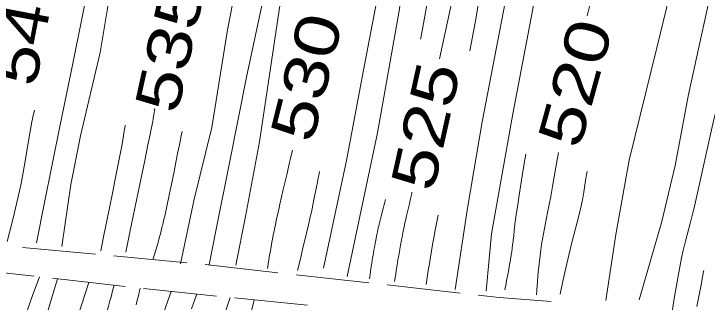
# Model space of a CAD drawing. Extents: x 2361284 to 2366480, y 6976556 to 6985346.
# Drawn here: x 2364811.3 to 2364887, y 6979187.4 to 6979218.9 of the extents above; entities that cross this region are included whole.
import ezdxf
from ezdxf.enums import TextEntityAlignment as Align

# ---------------------------------------------------------------- set-up
doc = ezdxf.new("R2010")
doc.units = 0
doc.header["$LTSCALE"] = 1.9
for name, color, linetype, lineweight in [('12', 7, 'Continuous', 13), ('13', 7, 'Continuous', 13), ('6', 7, 'Continuous', 13)]:
    doc.layers.add(name, color=color, linetype=linetype, lineweight=lineweight)

msp = doc.modelspace()

# ---------------------------------------------------------------- linework, layer by layer
at = {"layer": '12'}
for points in [[(2364928.338, 6979404.773), (2364927.195, 6979401.991), (2364924.932, 6979395.96), (2364922.532, 6979389.637), (2364919.419, 6979381.457), (2364916.6, 6979372.929), (2364914.535, 6979364.97), (2364911.915, 6979356.603), (2364906.81, 6979342.444), (2364903.391, 6979331.771), (2364900.674, 6979323.105), (2364897.677, 6979314.345), (2364893.693, 6979298.897), (2364889.623, 6979284.088), (2364887.079, 6979275.043), (2364882.952, 6979258.982), (2364879.363, 6979246.318), (2364877.403, 6979235.749), (2364874.144, 6979219.817), (2364873.874, 6979218.664)], [(2364892.809, 6979393.874), (2364890.358, 6979378.279), (2364887.083, 6979364.069), (2364883.826, 6979351.046), (2364881.758, 6979340.367), (2364879.074, 6979326.15), (2364876.929, 6979314.058), (2364874.851, 6979303.198), (2364871.819, 6979287.628), (2364868.255, 6979272.234), (2364866.777, 6979261.469), (2364864.79, 6979249.63), (2364863.428, 6979242.396), (2364861.678, 6979234.019), (2364859.472, 6979222.058), (2364857.728, 6979213.971)], [(2364826.658, 6979208.535), (2364826.633, 6979208.38), (2364826.588, 6979208.071), (2364826.529, 6979207.657), (2364826.497, 6979207.451), (2364826.473, 6979207.314), (2364826.461, 6979207.245), (2364826.441, 6979207.143), (2364826.269, 6979206.286), (2364826.153, 6979205.715), (2364825.92, 6979204.573), (2364825.566, 6979202.86), (2364824.854, 6979199.437), (2364823.944, 6979195.061), (2364823.487, 6979192.874)], [(2364841.682, 6979203.998), (2364841.479, 6979203.098), (2364841.341, 6979202.498), (2364841.063, 6979201.299), (2364840.69, 6979199.701), (2364840.505, 6979198.902), (2364840.32, 6979198.103), (2364840.229, 6979197.703), (2364840.049, 6979196.902), (2364839.96, 6979196.501), (2364839.829, 6979195.9), (2364839.791, 6979195.724), (2364839.718, 6979195.371), (2364839.646, 6979195.017), (2364839.6, 6979194.782), (2364839.51, 6979194.31), (2364839.444, 6979193.955), (2364839.402, 6979193.719), (2364839.318, 6979193.245), (2364839.278, 6979193.008), (2364839.197, 6979192.534), (2364839.119, 6979192.06), (2364838.965, 6979191.111)], [(2364870.726, 6979203.763), (2364870.429, 6979202.163), (2364870.068, 6979200.024), (2364869.882, 6979198.956), (2364869.546, 6979197.214), (2364869.086, 6979194.893), (2364868.881, 6979193.726), (2364868.789, 6979193.12), (2364868.64, 6979191.904), (2364868.524, 6979190.684), (2364868.344, 6979188.24)], [(2364854.737, 6979199.412), (2364854.707, 6979199.27), (2364854.646, 6979198.988), (2364854.583, 6979198.705), (2364854.541, 6979198.517), (2364854.454, 6979198.142), (2364854.321, 6979197.578), (2364854.144, 6979196.827), (2364854.057, 6979196.451), (2364853.973, 6979196.075), (2364853.933, 6979195.886), (2364853.873, 6979195.603), (2364853.828, 6979195.385), (2364853.741, 6979194.949), (2364853.656, 6979194.513), (2364853.601, 6979194.222), (2364853.493, 6979193.639), (2364853.414, 6979193.202), (2364853.363, 6979192.91), (2364853.262, 6979192.326), (2364853.212, 6979192.034), (2364853.116, 6979191.449), (2364853.021, 6979190.864), (2364852.959, 6979190.474), (2364852.838, 6979189.693)], [(2364822.232, 6979189.262), (2364822.028, 6979188.509), (2364821.925, 6979188.132), (2364821.768, 6979187.569), (2364821.608, 6979187.006), (2364821.526, 6979186.725), (2364821.382, 6979186.236), (2364821.285, 6979185.91), (2364821.09, 6979185.259), (2364820.794, 6979184.283), (2364820.198, 6979182.332)], [(2364837.507, 6979187.687), (2364837.181, 6979186.34), (2364837.003, 6979185.671), (2364836.805, 6979185.008), (2364836.696, 6979184.679), (2364836.065, 6979182.868), (2364834.767, 6979179.26), (2364833.262, 6979175.106), (2364832.486, 6979173.038), (2364832.245, 6979172.433), (2364832.075, 6979172.034), (2364831.722, 6979171.24), (2364830.612, 6979168.883), (2364830.076, 6979167.696), (2364829.575, 6979166.488), (2364828.928, 6979164.867), (2364828.591, 6979164.061), (2364828.332, 6979163.478), (2364828.153, 6979163.092), (2364827.78, 6979162.329), (2364827.188, 6979161.201), (2364826.774, 6979160.458), (2364826.491, 6979159.965), (2364825.909, 6979158.985)]]:
    msp.add_lwpolyline(points, dxfattribs=at)
at = {"layer": '13'}
for points in [[(2364953.546, 6979538.739), (2364951.73, 6979532.022), (2364949.096, 6979523.986), (2364946.595, 6979516.742), (2364944.83, 6979511.974), (2364942.013, 6979505.338), (2364937.966, 6979497.559), (2364932.421, 6979488.705), (2364927.679, 6979480.421), (2364924.672, 6979472.712), (2364920.626, 6979462.822), (2364915.322, 6979451.562), (2364911.657, 6979441.586), (2364906.137, 6979424.832), (2364900.236, 6979404.905), (2364894.169, 6979384.497), (2364889.513, 6979361.892), (2364883.686, 6979331.134), (2364880.421, 6979314.802), (2364874.826, 6979288.987), (2364868.833, 6979255.629), (2364866.279, 6979245.533), (2364861.641, 6979217.898), (2364861.05, 6979214.832)], [(2364870.103, 6979395.469), (2364866.361, 6979379.951), (2364863.768, 6979364.397), (2364858.988, 6979344.49), (2364855.217, 6979323.473), (2364852.338, 6979308.515), (2364848.685, 6979292.098), (2364845.65, 6979275.81), (2364842.581, 6979257.779), (2364839.483, 6979242.818), (2364836.913, 6979229.113), (2364834.587, 6979217.121), (2364832.899, 6979206.464), (2364830.952, 6979198.645), (2364829.469, 6979191.601)], [(2364872.305, 6979393.189), (2364867.085, 6979367.959), (2364862.537, 6979345.583), (2364857.126, 6979321.501), (2364853.57, 6979304.246), (2364849.37, 6979285.254), (2364845.525, 6979261.637), (2364841.654, 6979239.599), (2364839.108, 6979223.374), (2364836.677, 6979211.96), (2364834.805, 6979202.631), (2364833.346, 6979195.208), (2364832.601, 6979191.511)], [(2364902.442, 6979388.496), (2364898.909, 6979378.251), (2364895.442, 6979367.308), (2364892.52, 6979358.089), (2364889.421, 6979342.179), (2364886.214, 6979327.108), (2364884.203, 6979315.668), (2364880.832, 6979299.925), (2364878.956, 6979291.176), (2364875.438, 6979276.273), (2364872.987, 6979265.748), (2364868.907, 6979247.848), (2364866.977, 6979231.029), (2364864.729, 6979219.157), (2364862.384, 6979207.105), (2364860.783, 6979197.689), (2364859.458, 6979188.806)], [(2364888.857, 6979387.816), (2364886.14, 6979373.829), (2364883.35, 6979361.173), (2364880.672, 6979346.266), (2364877.552, 6979332.665), (2364875.39, 6979321.204), (2364871.524, 6979303.897), (2364867.73, 6979288.569), (2364865.626, 6979275.27), (2364863.491, 6979261.068), (2364861.737, 6979249.881), (2364859.594, 6979240.71), (2364857.911, 6979228.444), (2364855.687, 6979216.201), (2364855.668, 6979216.101)], [(2364885.633, 6979387.166), (2364879.447, 6979356.225), (2364870.017, 6979315.143), (2364865.32, 6979288.546), (2364859.944, 6979257.614), (2364855.756, 6979235.263), (2364853.339, 6979219.189), (2364850.975, 6979205.896), (2364847.654, 6979190.234)], [(2364908.008, 6979386.729), (2364903.974, 6979371.438), (2364899.674, 6979357.767), (2364895.945, 6979347.011), (2364892.112, 6979333.694), (2364889.415, 6979322.838), (2364884.695, 6979302.772), (2364881.671, 6979289.572), (2364879.366, 6979278.59), (2364876.57, 6979263.432), (2364874.19, 6979251.75), (2364872.324, 6979240.781), (2364870.172, 6979231.57), (2364867.728, 6979218.266), (2364865.746, 6979207.957), (2364863.41, 6979194.874), (2364862.829, 6979188.638)], [(2364882.393, 6979382.925), (2364876.991, 6979358.992), (2364873.041, 6979339.994), (2364870.539, 6979327.549), (2364867.213, 6979313.495), (2364862.876, 6979287.923), (2364860.619, 6979274.882), (2364858.117, 6979260.436), (2364856.169, 6979250.728), (2364854.778, 6979238.224), (2364852.316, 6979227.771), (2364849.45, 6979212.742), (2364847.603, 6979202.893), (2364845.065, 6979191.149)], [(2364872.908, 6979381.345), (2364870.69, 6979371.582), (2364864.338, 6979345.53), (2364860.311, 6979326.271), (2364855.806, 6979305.698), (2364851.796, 6979283.558), (2364847.901, 6979262.029), (2364843.719, 6979236.958), (2364841.197, 6979225.644), (2364838.094, 6979204.894), (2364836.561, 6979196.769), (2364835.502, 6979191.448)], [(2364849.396, 6979370.92), (2364848.573, 6979366.983), (2364846.03, 6979355.707), (2364843.156, 6979341.449), (2364840.627, 6979328.684), (2364838.817, 6979319.187), (2364836.411, 6979308.243), (2364834.31, 6979294.723), (2364831.344, 6979281.614), (2364829.098, 6979270.582), (2364827.546, 6979261.336), (2364824.695, 6979247.758), (2364822.56, 6979236.757), (2364819.459, 6979222.127), (2364817.77, 6979213.621), (2364816.287, 6979206.576), (2364814.635, 6979198.31), (2364813.737, 6979193.881)], [(2364852.165, 6979368.826), (2364851.189, 6979365.187), (2364847.016, 6979345.686), (2364844.515, 6979333.121), (2364842.126, 6979320.348), (2364839.41, 6979306.292), (2364836.59, 6979290.443), (2364833.659, 6979277.916), (2364831.377, 6979267.613), (2364828.568, 6979255.806), (2364826.566, 6979244.516), (2364824.743, 6979236.378), (2364822.147, 6979223.413), (2364820.71, 6979214.639), (2364818.566, 6979205.578), (2364817.497, 6979200.257), (2364816.501, 6979193.508)], [(2364915.38, 6979337.136), (2364914.087, 6979333.233), (2364911.656, 6979323.859), (2364908.063, 6979311.535), (2364904.289, 6979298.388), (2364900.534, 6979285.191), (2364898.513, 6979277.952), (2364895.361, 6979266.471), (2364892.013, 6979255.67), (2364889.124, 6979246.101), (2364887.027, 6979237.43), (2364884.644, 6979228.188), (2364881.448, 6979215.156), (2364878.456, 6979202.896), (2364876.973, 6979194.793), (2364875.911, 6979187.612)], [(2364905.775, 6979286.201), (2364903.391, 6979280.309), (2364900.005, 6979268.315), (2364897.509, 6979258.231), (2364895.171, 6979249.629), (2364892.48, 6979238.112), (2364889.821, 6979229.606), (2364887.246, 6979220.712), (2364884.937, 6979210.069), (2364883.48, 6979202.314), (2364882.028, 6979196.211), (2364879.54, 6979187.697)], [(2364894.255, 6979230.319), (2364893.205, 6979226.471), (2364892.659, 6979224.553), (2364890.596, 6979217.543), (2364888.944, 6979211.885), (2364888.137, 6979209.05), (2364887.983, 6979208.486), (2364887.694, 6979207.354), (2364887.424, 6979206.217), (2364886.905, 6979203.938), (2364885.534, 6979197.704), (2364885.41, 6979197.185), (2364885.142, 6979196.152), (2364884.588, 6979194.09), (2364884.338, 6979193.053), (2364884.167, 6979192.257), (2364883.861, 6979190.658), (2364883.358, 6979187.808), (2364883.122, 6979186.381)], [(2364813.54, 6979208.38), (2364813.367, 6979207.619), (2364813.215, 6979206.906), (2364813.122, 6979206.43), (2364812.952, 6979205.473), (2364812.493, 6979202.593), (2364812.238, 6979201.157), (2364812.078, 6979200.359), (2364811.733, 6979198.769), (2364811.357, 6979197.187), (2364811.094, 6979196.134), (2364810.546, 6979194.031)], [(2364823.446, 6979206.734), (2364823.394, 6979206.445), (2364823.361, 6979206.252), (2364823.296, 6979205.866), (2364823.171, 6979205.093), (2364823.106, 6979204.707), (2364823.06, 6979204.45), (2364823.037, 6979204.322), (2364823, 6979204.13), (2364822.856, 6979203.398), (2364822.566, 6979201.935), (2364822.273, 6979200.472), (2364822.077, 6979199.497), (2364821.683, 6979197.547), (2364821.073, 6979194.534), (2364820.766, 6979193.028)], [(2364829.651, 6979206.053), (2364829.554, 6979205.568), (2364829.358, 6979204.599), (2364829.16, 6979203.631), (2364828.763, 6979201.694), (2364828.441, 6979200.13), (2364828.224, 6979199.088), (2364827.787, 6979197.005), (2364827.748, 6979196.823), (2364827.668, 6979196.46), (2364827.583, 6979196.098), (2364827.525, 6979195.858), (2364827.486, 6979195.697), (2364827.405, 6979195.377), (2364827.312, 6979195.017), (2364827.248, 6979194.778), (2364827.118, 6979194.3), (2364827.052, 6979194.061), (2364826.917, 6979193.583), (2364826.78, 6979193.106), (2364826.503, 6979192.153)], [(2364867.148, 6979203.569), (2364867.027, 6979202.779), (2364866.781, 6979201.199), (2364866.451, 6979199.093), (2364866.287, 6979198.039), (2364866.125, 6979196.986), (2364866.045, 6979196.459), (2364866.031, 6979196.363), (2364866.004, 6979196.171), (2364865.98, 6979195.978), (2364865.964, 6979195.85), (2364865.935, 6979195.593), (2364865.894, 6979195.207), (2364865.843, 6979194.692), (2364865.816, 6979194.435), (2364865.788, 6979194.177), (2364865.773, 6979194.049), (2364865.75, 6979193.856), (2364865.726, 6979193.667), (2364865.675, 6979193.288), (2364865.621, 6979192.91), (2364865.583, 6979192.659), (2364865.557, 6979192.491), (2364865.504, 6979192.156), (2364865.442, 6979191.78), (2364865.399, 6979191.529), (2364865.309, 6979191.028), (2364865.263, 6979190.778), (2364865.169, 6979190.277), (2364865.071, 6979189.777), (2364865.004, 6979189.444), (2364864.868, 6979188.777)], [(2364844.635, 6979201.665), (2364844.563, 6979201.263), (2364844.514, 6979200.995), (2364844.413, 6979200.459), (2364844.361, 6979200.192), (2364844.256, 6979199.657), (2364844.149, 6979199.123), (2364844.076, 6979198.768), (2364843.926, 6979198.057), (2364843.869, 6979197.791), (2364843.753, 6979197.259), (2364843.635, 6979196.728), (2364843.555, 6979196.373), (2364843.394, 6979195.665), (2364843.271, 6979195.135), (2364843.188, 6979194.781), (2364843.02, 6979194.074), (2364842.765, 6979193.013), (2364842.594, 6979192.306), (2364842.247, 6979190.892)], [(2364873.846, 6979201.662), (2364873.787, 6979201.343), (2364873.691, 6979200.702), (2364873.514, 6979199.416), (2364873.394, 6979198.779), (2364873.236, 6979198.083), (2364872.898, 6979196.697), (2364872.194, 6979193.932), (2364871.863, 6979192.544), (2364871.222, 6979189.706), (2364870.913, 6979188.285)], [(2364851.844, 6979198.614), (2364851.819, 6979198.507), (2364851.767, 6979198.292), (2364851.713, 6979198.078), (2364851.676, 6979197.936), (2364851.6, 6979197.651), (2364851.368, 6979196.799), (2364851.293, 6979196.514), (2364851.256, 6979196.372), (2364851.185, 6979196.086), (2364851.151, 6979195.943), (2364851.102, 6979195.727), (2364851.056, 6979195.515), (2364850.966, 6979195.09), (2364850.88, 6979194.664), (2364850.824, 6979194.381), (2364850.787, 6979194.191), (2364850.715, 6979193.812), (2364850.637, 6979193.385), (2364850.586, 6979193.1), (2364850.488, 6979192.53), (2364850.44, 6979192.245), (2364850.347, 6979191.674), (2364850.257, 6979191.102), (2364850.199, 6979190.721), (2364850.086, 6979189.957)], [(2364857.59, 6979196.929), (2364857.272, 6979195.279), (2364857.114, 6979194.454), (2364857.078, 6979194.266), (2364857.009, 6979193.889), (2364856.942, 6979193.512), (2364856.899, 6979193.26), (2364856.815, 6979192.756), (2364856.754, 6979192.378), (2364856.714, 6979192.126), (2364856.636, 6979191.621), (2364856.523, 6979190.863), (2364856.302, 6979189.346)], [(2364814.063, 6979190.184), (2364813.283, 6979188.027), (2364812.046, 6979184.505), (2364811.462, 6979182.765), (2364810.706, 6979180.437), (2364810.316, 6979179.277), (2364809.846, 6979177.976), (2364809.516, 6979177.116), (2364808.832, 6979175.403), (2364808.126, 6979173.681), (2364807.752, 6979172.829), (2364807.352, 6979171.991), (2364807.138, 6979171.578), (2364805.497, 6979168.542), (2364803.138, 6979164.219)], [(2364816.055, 6979189.953), (2364815.143, 6979186.945), (2364813.554, 6979181.568), (2364813.321, 6979180.817), (2364812.831, 6979179.323), (2364812.315, 6979177.837), (2364811.248, 6979174.876), (2364810.719, 6979173.458), (2364810.351, 6979172.52), (2364809.588, 6979170.651), (2364809.242, 6979169.84), (2364809.005, 6979169.303), (2364808.516, 6979168.237), (2364808.264, 6979167.707), (2364807.747, 6979166.654), (2364807.212, 6979165.609), (2364806.847, 6979164.916), (2364806.095, 6979163.537)], [(2364819.469, 6979189.576), (2364818.633, 6979186.978), (2364817.787, 6979184.44), (2364816.994, 6979182.011), (2364815.952, 6979178.767), (2364815.427, 6979177.146), (2364814.934, 6979175.697), (2364814.59, 6979174.736), (2364813.878, 6979172.821), (2364813.432, 6979171.674), (2364813.121, 6979170.915), (2364812.908, 6979170.413), (2364812.468, 6979169.414), (2364812.125, 6979168.67), (2364811.41, 6979167.196), (2364810.655, 6979165.738), (2364810.13, 6979164.775), (2364809.771, 6979164.136), (2364809.032, 6979162.865)], [(2364825.074, 6979188.939), (2364824.972, 6979188.503), (2364824.92, 6979188.285), (2364824.84, 6979187.959), (2364824.758, 6979187.634), (2364824.715, 6979187.472), (2364824.628, 6979187.148)], [(2364828.447, 6979188.601), (2364828.107, 6979187.671), (2364827.454, 6979185.802)], [(2364834.895, 6979187.942), (2364834.117, 6979185.645), (2364832.648, 6979181.33), (2364832.175, 6979179.894), (2364831.549, 6979177.978), (2364831.218, 6979177.026), (2364831.006, 6979176.457), (2364830.55, 6979175.331), (2364830.065, 6979174.217), (2364829.402, 6979172.737), (2364829.075, 6979171.996), (2364827.702, 6979168.892), (2364826.999, 6979167.346), (2364826.583, 6979166.467), (2364826.294, 6979165.887), (2364825.693, 6979164.739), (2364825.381, 6979164.172), (2364824.736, 6979163.047), (2364824.068, 6979161.934), (2364823.61, 6979161.198), (2364822.672, 6979159.735)], [(2364831.261, 6979188.318), (2364830.667, 6979186.703)]]:
    msp.add_lwpolyline(points, dxfattribs=at)
at = {"layer": '6'}
for p, q in [((2364820.199, 6979192.643), (2364812.232, 6979193.377)), ((2364830.158, 6979191.728), (2364822.191, 6979192.462)), ((2364840.099, 6979190.642), (2364832.15, 6979191.546)), ((2364805.542, 6979191.143), (2364813.492, 6979190.249)), ((2364815.484, 6979190.028), (2364823.433, 6979189.123)), ((2364850.04, 6979189.526), (2364842.092, 6979190.421)), ((2364859.982, 6979188.411), (2364852.033, 6979189.305)), ((2364825.424, 6979188.902), (2364833.383, 6979188.098)), ((2364835.375, 6979187.897), (2364843.333, 6979187.093))]:
    msp.add_line(p, q, dxfattribs=at)
for points in [[(2364885.837, 6979186.947), (2364885.99, 6979187.668), (2364886.133, 6979188.39), (2364886.332, 6979189.512), (2364886.532, 6979190.633), (2364886.579, 6979190.874)], [(2364869.941, 6979187.486), (2364864.266, 6979187.932), (2364861.974, 6979188.19)]]:
    msp.add_lwpolyline(points, dxfattribs=at)

# ---------------------------------------------------------------- texts
at = {"layer": '12'}
for s, rotation, width, p in [(' 540 ', 79.18, 1.25, (2364814.885, 6979217.346)), (' 535 ', 77.543, 1.3, (2364830.62, 6979214.624)), (' 530 ', 75.975, 1.3, (2364845.548, 6979211.391)), (' 520 ', 74.584, 1.3, (2364874.873, 6979210.697)), (' 525 ', 77.453, 1.3, (2364858.572, 6979206.123))]:
    msp.add_text(s, height=4.8, rotation=rotation, dxfattribs=dict(at, width=width)).set_placement(p, align=Align.CENTER)

doc.saveas('drawing.dxf')
